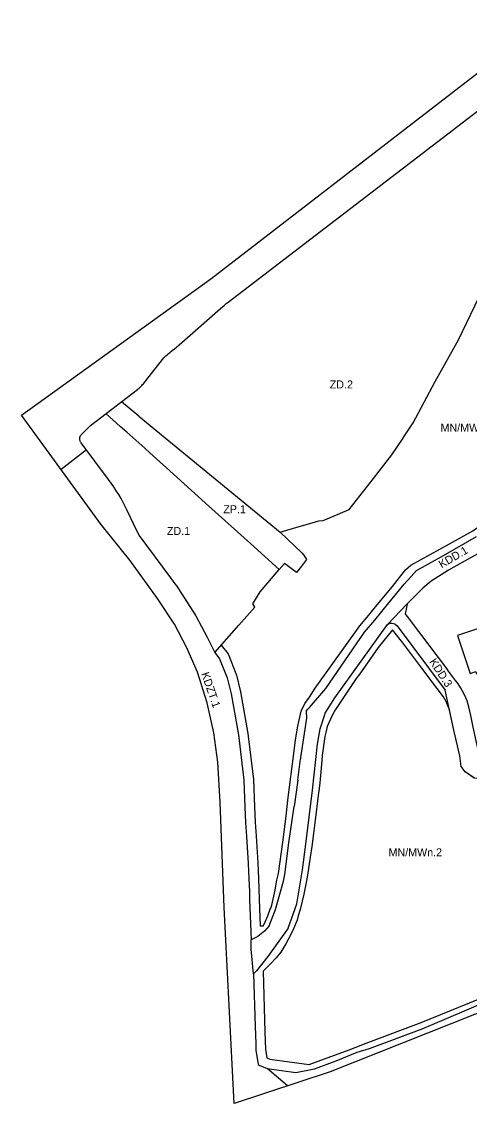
# Model space of a CAD drawing. Extents: x 7427074 to 7428708, y 5545888 to 5547145.
# Drawn here: x 7427074 to 7427353, y 5545936 to 5546612 of the extents above; entities that cross this region are included whole.
import ezdxf

# ---------------------------------------------------------------- set-up
doc = ezdxf.new("R2010")
doc.units = 0
for name, color, linetype in [('linie_rozgraniczajace', 7, 'Continuous'), ('linie_zabudowy_nieprzekraczalne', 7, 'Continuous'), ('linie_zabudowy_obowiazujace', 7, 'Continuous'), ('oznaczenia_przeznaczen', 7, 'Continuous')]:
    doc.layers.add(name, color=color, linetype=linetype)

msp = doc.modelspace()

# ---------------------------------------------------------------- linework, layer by layer
at = {"layer": 'linie_rozgraniczajace'}
for p, q in [((7427245.64, 5546492.63), (7427400.2, 5546611.86)), ((7427332.14, 5546387.11), (7427346.74, 5546412.98)), ((7427318.25, 5546361.12), (7427332.14, 5546387.11)), ((7427146.94, 5546365.32), (7427135.93, 5546374.36)), ((7427305, 5546341.28), (7427311.99, 5546351.66)), ((7427114.09, 5546344.29), (7427098.26, 5546332.06)), ((7427262.13, 5546300.28), (7427278.26, 5546307.11)), ((7427234.65, 5546269.69), (7427216.7, 5546285.84)), ((7427222.64, 5546255.69), (7427234.65, 5546269.69)), ((7427171.74, 5546257.45), (7427182.49, 5546240.56)), ((7427308.21, 5546234.46), (7427338.39, 5546194.15)), ((7427343.73, 5546169.24), (7427338.39, 5546194.15)), ((7427251.51, 5546181.17), (7427252.53, 5546182.29)), ((7427246.12, 5546137.89), (7427244.02, 5546121.61)), ((7427218.54, 5546017), (7427219.56, 5545984.17)), ((7427239.78, 5545946.98), (7427227.07, 5545957.92))]:
    msp.add_line(p, q, dxfattribs=at)
for points in [[(7427202.76, 5546436.65), (7427362.2, 5546558.93)], [(7427073.59, 5546366.01), (7427191.84, 5546451.13), (7427245.64, 5546492.63)], [(7427346.74, 5546412.98), (7427359.35, 5546439.56)], [(7427172.02, 5546409.92), (7427197.9, 5546432.65)], [(7427197.9, 5546432.65), (7427199.09, 5546433.68), (7427200.29, 5546434.69), (7427201.52, 5546435.68), (7427202.76, 5546436.65)], [(7427165.21, 5546404.38), (7427166.23, 5546405.16)], [(7427166.23, 5546405.16), (7427167.71, 5546406.32), (7427169.16, 5546407.49), (7427170.6, 5546408.69), (7427172.02, 5546409.92)], [(7427150.18, 5546386.22), (7427162.51, 5546401.73)], [(7427162.51, 5546401.73), (7427163.12, 5546402.45), (7427163.78, 5546403.14), (7427164.48, 5546403.78), (7427165.21, 5546404.38)], [(7427145.91, 5546382.02), (7427146.5, 5546382.48), (7427147.07, 5546382.97), (7427147.63, 5546383.47), (7427148.17, 5546383.99), (7427148.7, 5546384.52), (7427149.21, 5546385.07), (7427149.71, 5546385.64), (7427150.18, 5546386.22)], [(7427116.62, 5546359.56), (7427145.91, 5546382.02)], [(7427402.2, 5546009.67), (7427266.44, 5545955.68), (7427206.38, 5545936.07), (7427200.25, 5546058.47), (7427197.66, 5546124.3), (7427196.19, 5546149.15), (7427193.78, 5546167.48), (7427189.51, 5546186.26), (7427183.43, 5546205.4), (7427176.79, 5546220.59), (7427169.1, 5546235.35), (7427158.46, 5546251.47), (7427141.17, 5546275.37), (7427123.08, 5546297.92), (7427073.59, 5546366.01)], [(7427139.29, 5546355.38), (7427135.24, 5546358.99), (7427126.31, 5546366.98)], [(7427146.94, 5546365.32), (7427163.3, 5546351.88), (7427170.28, 5546346.15)], [(7427111.06, 5546354.01), (7427115.79, 5546358.82)], [(7427115.79, 5546358.82), (7427116.19, 5546359.2), (7427116.62, 5546359.56)], [(7427311.99, 5546351.66), (7427312.15, 5546351.91), (7427318.25, 5546361.12)], [(7427110.71, 5546348.81), (7427110.52, 5546349.08), (7427110.35, 5546349.37), (7427110.21, 5546349.69), (7427110.09, 5546350.02), (7427110, 5546350.37), (7427109.94, 5546350.73), (7427109.91, 5546351.1), (7427109.92, 5546351.47), (7427109.96, 5546351.84), (7427110.04, 5546352.2), (7427110.14, 5546352.55), (7427110.28, 5546352.88), (7427110.44, 5546353.2), (7427110.63, 5546353.49), (7427110.84, 5546353.76), (7427111.06, 5546354.01)], [(7427153.65, 5546342.58), (7427150.53, 5546345.35), (7427139.29, 5546355.38)], [(7427127.95, 5546325.79), (7427110.71, 5546348.81)], [(7427170.28, 5546346.15), (7427235.21, 5546292.83), (7427247.08, 5546296.55), (7427255.22, 5546298.68), (7427259.43, 5546299.9), (7427262.13, 5546300.28)], [(7427479.26, 5546349.84), (7427467.13, 5546341.73), (7427458.44, 5546335.98), (7427442.11, 5546325.17), (7427425.1, 5546314.77), (7427419.81, 5546311.95), (7427414.6, 5546309.15), (7427402.89, 5546302.98), (7427380.2, 5546291.01), (7427369.27, 5546285.25), (7427354.06, 5546276.83), (7427340.36, 5546269.25), (7427329.45, 5546262.24), (7427324.29, 5546258.02), (7427314.5, 5546248.22), (7427302.27, 5546235.33)], [(7427216.7, 5546285.84), (7427190.68, 5546309.11), (7427179.54, 5546319.23), (7427164.06, 5546333.19), (7427153.65, 5546342.58)], [(7427278.26, 5546307.11), (7427292.07, 5546324.55), (7427305, 5546341.28)], [(7427139.63, 5546306.46), (7427138.39, 5546308.99), (7427137.08, 5546311.5), (7427135.71, 5546313.97), (7427134.28, 5546316.42), (7427132.78, 5546318.82), (7427131.23, 5546321.18), (7427129.62, 5546323.51), (7427127.95, 5546325.79)], [(7427145.63, 5546293.84), (7427139.63, 5546306.46)], [(7427147.05, 5546290.94), (7427145.63, 5546293.84)], [(7427170.2, 5546259.87), (7427166.85, 5546264.36), (7427147.05, 5546290.94)], [(7427235.21, 5546292.83), (7427239.74, 5546288.47), (7427248.63, 5546279.91), (7427250, 5546278.59), (7427251.61, 5546275.75), (7427248.51, 5546271.71), (7427245.37, 5546267.63), (7427237.94, 5546273.32), (7427234.65, 5546269.69)], [(7427252.53, 5546182.29), (7427253.53, 5546183.4), (7427263.63, 5546195.34), (7427287.9, 5546230.37), (7427294.44, 5546237.99), (7427303.18, 5546248.76), (7427308.07, 5546254.8), (7427312.71, 5546260.46), (7427317.04, 5546265.19), (7427320.42, 5546268.88), (7427337.22, 5546278.25), (7427357.81, 5546290.12)], [(7427170.2, 5546259.87), (7427171.74, 5546257.45)], [(7427194.32, 5546217.8), (7427209.32, 5546234.73), (7427219.32, 5546245.96), (7427218.03, 5546248.13), (7427222.64, 5546255.69)], [(7427314.5, 5546248.22), (7427313.87, 5546244.74), (7427313.35, 5546241.87)], [(7427182.49, 5546240.56), (7427189.45, 5546227.28), (7427194.32, 5546217.8), (7427197.3, 5546213.84), (7427202.1, 5546201.81), (7427204.51, 5546191.96), (7427209.12, 5546166.23), (7427212.51, 5546138.02), (7427213.16, 5546121.12), (7427213.55, 5546111.49), (7427214.1, 5546102.71), (7427215.18, 5546085.9), (7427215.49, 5546081), (7427215.66, 5546076.28), (7427215.93, 5546068.33), (7427216.1, 5546063.34), (7427216.96, 5546038.17)], [(7427302.27, 5546235.33), (7427303.54, 5546236.06), (7427305.26, 5546236.13), (7427306.82, 5546235.66), (7427308.21, 5546234.46)], [(7427313.35, 5546241.87), (7427313.58, 5546241.5), (7427314.8, 5546239.98), (7427315.21, 5546239.44), (7427315.79, 5546238.65), (7427339.68, 5546206.95)], [(7427240.09, 5546045.56), (7427244.57, 5546057.91), (7427245.5, 5546060.8), (7427249.08, 5546082.07), (7427251.29, 5546097.96), (7427255.36, 5546131.78), (7427258.41, 5546160.57), (7427260.15, 5546170.03), (7427262.79, 5546178.39), (7427263.37, 5546179.87), (7427269.41, 5546189.5), (7427302.27, 5546235.33)], [(7427362.96, 5546138.85), (7427355.8, 5546171.15), (7427354.86, 5546176.31), (7427354.43, 5546178.33), (7427353.09, 5546183.9), (7427352.09, 5546187.59), (7427350.29, 5546191.37), (7427347.87, 5546195.85), (7427345.98, 5546198.7), (7427344.73, 5546200.27), (7427339.68, 5546206.95)], [(7427251.51, 5546181.17), (7427251.68, 5546176.78), (7427247.96, 5546152.22), (7427247.84, 5546151.25)], [(7427348.4, 5546146.53), (7427347.37, 5546153.23), (7427343.73, 5546169.24)], [(7427246.12, 5546137.89), (7427247.84, 5546151.25)], [(7427362.96, 5546138.85), (7427356.47, 5546139.32), (7427350.7, 5546143.17), (7427348.4, 5546146.53)], [(7427228.39, 5546046.94), (7427232.22, 5546057.17), (7427237.3, 5546074.99), (7427238.09, 5546078.95), (7427240.65, 5546098.93), (7427244.02, 5546121.61)], [(7427228.39, 5546046.94), (7427225.47, 5546043.6), (7427221.29, 5546040.34), (7427216.96, 5546038.17)], [(7427240.09, 5546045.56), (7427227.49, 5546027.8), (7427220.49, 5546018.96), (7427218.54, 5546017)], [(7427218.54, 5546017), (7427217.15, 5546032.32), (7427216.96, 5546038.17)], [(7427245.02, 5545955.38), (7427256.58, 5545957.63), (7427270.25, 5545962.61), (7427283.36, 5545968.11), (7427291.06, 5545970.44), (7427323.88, 5545982.69), (7427337.78, 5545988.56), (7427365.93, 5546000.51), (7427376.94, 5546004.95), (7427391.87, 5546011.19), (7427406.37, 5546016.93), (7427406.37, 5546016.93)], [(7427219.56, 5545984.17), (7427219.89, 5545973.56), (7427220.01, 5545969.38), (7427221.38, 5545960.33), (7427222.09, 5545960.03)], [(7427222.09, 5545960.03), (7427227.07, 5545957.92), (7427245.02, 5545955.38)]]:
    msp.add_lwpolyline(points, dxfattribs=at)
at = {"layer": 'linie_zabudowy_nieprzekraczalne'}
for p, q in [((7427343.73, 5546169.24), (7427340.99, 5546182.02)), ((7427224.46, 5546046.77), (7427225.99, 5546049.8)), ((7427289.02, 5545973.59), (7427323.35, 5545986.61)), ((7427262.91, 5545963.8), (7427278.31, 5545969.52)), ((7427253.39, 5545960.25), (7427262.91, 5545963.8))]:
    msp.add_line(p, q, dxfattribs=at)
for points in [[(7427257.14, 5546195.43), (7427285.02, 5546234.34), (7427290.57, 5546240.98), (7427293.76, 5546244.92), (7427305.32, 5546258.92), (7427313.52, 5546269.3), (7427316.86, 5546272.22), (7427340.92, 5546285.7), (7427355.54, 5546293.85), (7427357.88, 5546295.45), (7427365.28, 5546299.95), (7427382.65, 5546309.18), (7427384.23, 5546310.01), (7427404.8, 5546319.28), (7427408.61, 5546321.5), (7427431.21, 5546333.63), (7427456.78, 5546349.28), (7427464.99, 5546355.87)], [(7427305.31, 5546232), (7427296.45, 5546220.76), (7427284.99, 5546204.5)], [(7427323.76, 5546207.87), (7427311.8, 5546223.71), (7427305.31, 5546232)], [(7427198.38, 5546222.38), (7427202.58, 5546216.81), (7427207.83, 5546203.64), (7427210.38, 5546193.2), (7427215.06, 5546167.12), (7427218.5, 5546138.49), (7427219.16, 5546121.36), (7427219.54, 5546111.8), (7427220.09, 5546103.09), (7427221.17, 5546086.28), (7427221.48, 5546081.3), (7427221.66, 5546076.49), (7427222.1, 5546063.54), (7427222.67, 5546046.69)], [(7427284.9, 5546204.37), (7427282.69, 5546201.41), (7427275.25, 5546190.16), (7427269.73, 5546182.08), (7427268.18, 5546179.31), (7427266.54, 5546176.05), (7427264.63, 5546171.53), (7427263.64, 5546167.73), (7427263.16, 5546165.2), (7427261.33, 5546153.47), (7427261.23, 5546150.26)], [(7427340.99, 5546182.02), (7427338.84, 5546187.03), (7427337.23, 5546190.11), (7427333.28, 5546195.24), (7427323.76, 5546207.88)], [(7427243.73, 5546154.6), (7427244.68, 5546163.25), (7427246.2, 5546171.79), (7427248.31, 5546181.16), (7427250.67, 5546185.79), (7427253.56, 5546189.86), (7427257.14, 5546195.43)], [(7427348.4, 5546146.53), (7427347.37, 5546153.23), (7427343.73, 5546169.24)], [(7427238.87, 5546115.54), (7427239.56, 5546121.55), (7427240.28, 5546127.12), (7427243.73, 5546154.6)], [(7427261.23, 5546150.26), (7427260.37, 5546140.91), (7427259.9, 5546136.22), (7427259.51, 5546132.74), (7427258.93, 5546128.32), (7427257.13, 5546113.03), (7427256.06, 5546104.66), (7427254.89, 5546096.53), (7427254, 5546089.97), (7427252.28, 5546078.66), (7427251.5, 5546074.04), (7427250.69, 5546069.81), (7427250.04, 5546066.72)], [(7427356.43, 5546139.35), (7427350.7, 5546143.17), (7427348.4, 5546146.53)], [(7427232.05, 5546069.42), (7427232.07, 5546069.51), (7427233.19, 5546075.41), (7427234.1, 5546079.71), (7427236.85, 5546099.3), (7427238.87, 5546115.54)], [(7427250.04, 5546066.72), (7427247.61, 5546057.09), (7427246.53, 5546053.13), (7427245.74, 5546050.54), (7427243.58, 5546045.19), (7427241.63, 5546041.06), (7427238.67, 5546035.7), (7427235.53, 5546030.61), (7427232.65, 5546026.99), (7427229.2, 5546023.2), (7427224.49, 5546018.72)], [(7427230.36, 5546061.79), (7427230.37, 5546061.81), (7427232.03, 5546069.33), (7427232.05, 5546069.42)], [(7427229.26, 5546057.98), (7427229.28, 5546058.03), (7427229.92, 5546059.82), (7427230.36, 5546061.78), (7427230.36, 5546061.79)], [(7427225.99, 5546049.8), (7427227.42, 5546053.13), (7427229.24, 5546057.92), (7427229.26, 5546057.98)], [(7427224.46, 5546046.77), (7427222.67, 5546046.69)], [(7427224.49, 5546018.72), (7427225.68, 5545980.46)], [(7427323.35, 5545986.61), (7427371.5, 5546006.19), (7427386.29, 5546011.96)], [(7427225.68, 5545980.46), (7427226.01, 5545969.84), (7427226.81, 5545964.55)], [(7427278.31, 5545969.52), (7427282.07, 5545970.94), (7427289.02, 5545973.59)], [(7427226.81, 5545964.55), (7427228.69, 5545963.75), (7427253.39, 5545960.25)]]:
    msp.add_lwpolyline(points, dxfattribs=at)
at = {"layer": 'linie_zabudowy_obowiazujace'}
msp.add_lwpolyline([(7427353.99, 5546204.69), (7427357.4, 5546205.83), (7427357.84, 5546204.5), (7427360.5, 5546205.39), (7427360.06, 5546206.71), (7427366.18, 5546208.76), (7427366.62, 5546207.43), (7427369.28, 5546208.32), (7427368.83, 5546209.65), (7427372.25, 5546210.79), (7427365.85, 5546229.84), (7427367.09, 5546230.25), (7427366.57, 5546231.78), (7427366, 5546233.48), (7427365.57, 5546234.15), (7427364.84, 5546234.46), (7427364.11, 5546234.43), (7427346.05, 5546228.37)], close=True, dxfattribs=at)

# ---------------------------------------------------------------- texts
at = {"layer": 'oznaczenia_przeznaczen'}
for s, p in [('ZD.2', (7427266.17, 5546382.7)), ('MN/MWn.1', (7427335.44, 5546355.7)), ('ZP.1', (7427199.65, 5546304.78)), ('ZD.1', (7427164.4, 5546291.17)), ('MN/MWn.2', (7427302.94, 5546090.41))]:
    msp.add_text(s, height=5, dxfattribs=at).set_placement(p)
for s, rotation, p in [('KDD.1', 30.28288, (7427336.08, 5546270.22)), ('KDD.3', 303.25035, (7427328.19, 5546211.98)), ('KDZT.1', 289.14181, (7427185.76, 5546204.48))]:
    msp.add_text(s, height=5, rotation=rotation, dxfattribs=at).set_placement(p)

doc.saveas('drawing.dxf')
